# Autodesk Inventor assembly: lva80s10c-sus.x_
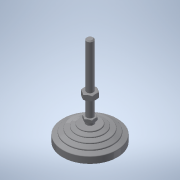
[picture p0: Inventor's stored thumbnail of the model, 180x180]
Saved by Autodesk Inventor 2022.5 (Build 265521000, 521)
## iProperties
Part Number: lva80s10c-sus.x_
Material: 一般
Document SubType Name: Assembly
Designer: ImaoCorp
Sending System: SOLIDWORKS 2017-2017317
MC: AMD64
MC_MODEL: Intel64 Family 6 Model 60 Stepping 3, GenuineIntel
OS: Windows_NT
FRU: Parasolid Version 29.0, build 201,  4-17-2017
FORMAT: text
GUISE: transmit
KEY: lva80s10c-sus
FILE: lva80s10c-sus.x_t
DATE: Mon Jul 01 18:09:35 2019
Author: ImaoCorp
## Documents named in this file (3)
- X:\14_SW2022-Inv2022\00_全2023-1023新製品(TCC)まで\l\lva80s10c-sus\LVA80S10C-SUS.iam
- X:\14_SW2022-Inv2022\00_全2023-1023新製品(TCC)まで\l\lva80s10c-sus\lva80s10c-sus_01.ipt
- X:\14_SW2022-Inv2022\00_全2023-1023新製品(TCC)まで\l\lva80s10c-sus\lva80s10c-sus_02.ipt
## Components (2 placed, 2 different names)
1. lva80s10c-sus_01
2. lva80s10c-sus_02
